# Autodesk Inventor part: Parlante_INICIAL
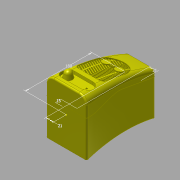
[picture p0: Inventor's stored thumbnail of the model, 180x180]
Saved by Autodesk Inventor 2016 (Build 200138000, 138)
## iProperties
Created: 2013-03
Part Number: Parlante_INICIAL
Material: Polycarbonate, Clear
Document SubType Name: Modeling
Designer: julian.chica
Density: 1 g/cm^3
Appearance: Smooth - Yellow
Author: julian.chica
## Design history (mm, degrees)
sketch "Sketch2"
  geometry: L1 (55, 75)-(-55, 75); L2 (-55, 75)-(-55, -75); L3 (-55, -75)-(55, -75); L4 (55, -75)-(55, 75); L5 (55, 75)-(-55, -75); L6 (-55, 75)-(55, -75); 1 further point
  constraints: 12 end point, 2 midpoint, 2 parallel, 1 horizontal, 1 perpendicular
  dimensions: "d0" = 150 distance of L3.end L1.start; "d2" = 110 distance of L1.start L1.end
sketch "Sketch3"
  geometry: A1 r 500 centre (0, -425) between (200, 33.258) and (0, 75); 3 further points
  constraints: 2 point on circle, 1 centre point, 1 vertical alignment
  dimensions: "d3" = 500 radius of A1; "d5" = 200 horizontal distance of point (0, 0) A1.start
sketch "Sketch4"
  geometry: L1 (0, 0)-(200, -17.498); L2 (0, 0)-(0, -219.032); 2 further points
  constraints: 4 end point, 1 coincident, 1 vertical, 1 vertical alignment
  dimensions: "d6" = 85 deg angle of L2 L1
workplane "Work Plane1"
sketch "Sketch5"
  geometry: L1 (-40, 50.755)-(40, 50.755); L2 (40, 50.755)-(40, -64.245); L3 (40, -64.245)-(-40, -64.245); L4 (-40, -64.245)-(-40, 50.755); 3 further points
  constraints: 8 end point, 2 parallel, 1 horizontal, 1 midpoint, 1 perpendicular
  dimensions: "d7" = 115 distance between parallel lines of L3 L1; "d10" = 80 distance of L1.start L1.end; "d11" = 40 distance from line of point (0, 0) L4
loft "Loft1" sketch "Sketch5" dims "d12" = 0, "d13" = 90 deg, "d14" = 0, "d15" = 90 deg, "d16" = 0, "d17" = 90 deg
sketch "Sketch6"
  geometry: L1 (210, 13.258)-(104.31, 38.532); L2 (74.895, 38.152)-(33.172, 27.026); L3 (17.712, 25)-(-10, 25); L4 (200, 33.258)-(200, -81.742) reference; L5 (0, 75)-(0, -75) reference; A1 r 60 centre (90.355, -19.822) between (104.31, 38.532) and (74.895, 38.152); A2 r 60 centre (17.712, 85) between (17.712, 25) and (33.172, 27.026); 1 further point
  constraints: 6 end point, 4 point on circle, 4 tangent, 2 centre point, 1 equal radius, 1 horizontal
  dimensions: "d20" = 60 radius of A1; "d21" = 10 distance from line of L1.start L4; "d22" = 10 distance from line of L3.end L5; "d23" = 20 vertical distance of L4.start L1.start; "d24" = 50 vertical distance of L5.start L3.end
extrude_surface "ExtrusionSrf1" dims "d29" = 131.5, "d30" = 0
fillet "Fillet1" dims "d25" = 21.25, "d26" = 10, "d27" = 21.25, "d28" = 10
fillet "Fillet2" dims "d31" = 4
fillet "Fillet3" dims "d32" = 2
shell "Shell2" dims "d176" = 2.5
split "Split2"
  body "Solid1"
feature "Lip3" dims "d177" = 1.9, "d178" = 1.22, "d179" = 0, "d180" = 0.12217, "d181" = 0.12217, "d182" = 1.3
feature "Lip4" dims "d183" = 2, "d184" = 1.2, "d185" = 0, "d186" = 0.06981, "d187" = 0, "d188" = 0.2
workplane "Work Plane2"
sketch "Sketch7"
  geometry: L1 (-25, 47)-(25, 47); L2 (25, 47)-(25, 13); L3 (25, 13)-(-25, 13); L4 (-25, 13)-(-25, 47); L5 (-25, 47)-(25, 13); L6 (25, 47)-(-25, 13); A1 r 17 centre (-25, 30) between (-25, 47) and (-25, 13); A2 r 17 centre (25, 30) between (25, 13) and (25, 47); 3 further points
  constraints: 12 end point, 5 midpoint, 4 point on circle, 2 centre point, 2 parallel, 1 horizontal, 1 perpendicular, 1 vertical alignment
  dimensions: "d54" = 17 radius of A1; "d56" = 50 distance of L1.start L1.end; "d57" = 13 distance from line of L3 point (0, 0)
feature "Rest4" sketch "Sketch7" dims "d189" = 5, "d190" = 0, "d191" = 0, "d192" = 0, "d193" = 0, "d194" = 10 deg, "d195" = 1
workplane "Work Plane3"
sketch "Sketch8"
  geometry: L1 (25, 14)-(-25, 14) reference; 4 further points
  constraints: 1 horizontal alignment, 1 vertical alignment
  dimensions: "d73" = 180 vertical distance of point (-21, 180) point (0, 0); "d74" = 21 horizontal distance of point (-21, 180) point (0, 0); "d75" = 21 horizontal distance of point (0, 29) point (21, 180); "d196" = 15 distance from line of L1 point (0, 29)
feature "Boss3" dims "d197" = 0, "d198" = 0, "d199" = 8, "d200" = 3, "d201" = 9.5, "d202" = 1.5 deg, "d203" = 1 deg, "d206" = 2, "d207" = 2, "d208" = 5, "d209" = 0, "d210" = 9 deg, "d211" = 1.5 deg, "d212" = 0.25, "d213" = 0, "d214" = 0, "d215" = 360 deg
feature "Boss4" dims "d216" = 0, "d217" = 0, "d218" = 9, "d219" = 2, "d220" = 0.5, "d221" = 8.1, "d222" = 1.25, "d223" = 3.5, "d224" = 2.5 deg, "d225" = 2.5 deg, "d226" = 2.5 deg, "d227" = 2.5 deg, "d228" = 90 deg, "d231" = 1.5, "d232" = 2, "d233" = 5, "d234" = 0, "d235" = 9 deg, "d236" = 1 deg, "d237" = 0.25, "d238" = 0, "d239" = 0, "d240" = 360 deg
workplane "Work Plane4"
sketch "Sketch9" dims "d131" = 10, "d154" = 10
  geometry: L1 (-37.5, 120)-(37.5, 120); L2 (37.5, 120)-(37.5, 70); L3 (27.5, 60)-(-27.5, 60); L4 (-37.5, 70)-(-37.5, 120); L5 (-37.5, 120)-(37.5, 60); L6 (37.5, 120)-(-37.5, 60); L7 (0, 49.71)-(0, 187.485); L8 (-47.214, 175.937)-(0, 152.413); L9 (-47.214, 169.937)-(0, 146.413); L10 (-47.214, 163.937)-(0, 140.413); L11 (-47.214, 157.937)-(0, 134.413); L12 (-47.214, 151.937)-(0, 128.413); L13 (-47.214, 145.937)-(0, 122.413); L14 (-47.214, 139.937)-(0, 116.413); L15 (-47.214, 133.937)-(0, 110.413); L16 (-47.214, 127.937)-(0, 104.413); L17 (-47.214, 121.937)-(0, 98.413); L18 (-47.214, 115.937)-(0, 92.413); L19 (-47.214, 109.937)-(0, 86.413); L20 (-47.214, 103.937)-(0, 80.413); L21 (-47.214, 97.937)-(0, 74.413); L22 (47.214, 175.937)-(0, 152.413); L23 (47.214, 169.937)-(0, 146.413); L24 (47.214, 151.937)-(0, 128.413); L25 (47.214, 145.937)-(0, 122.413); L26 (47.214, 139.937)-(0, 116.413); L27 (47.214, 133.937)-(0, 110.413); L28 (47.214, 163.937)-(0, 140.413); L29 (47.214, 157.937)-(0, 134.413); L30 (47.214, 127.937)-(0, 104.413); L31 (47.214, 121.937)-(0, 98.413); L32 (47.214, 109.937)-(0, 86.413); L33 (47.214, 103.937)-(0, 80.413); L34 (47.214, 115.937)-(0, 92.413); L35 (47.214, 97.937)-(0, 74.413); L36 (-21, 168.94)-(-21, 53.316); L37 (21, 168.94)-(21, 53.316); L38 (-47.214, 91.937)-(0, 68.413); L39 (47.214, 91.937)-(0, 68.413); L40 (-47.214, 85.937)-(0, 62.413); L41 (47.214, 85.937)-(0, 62.413); L42 (-47.214, 79.937)-(0, 56.413); L43 (47.214, 79.937)-(0, 56.413); L44 (-47.214, 73.937)-(0, 50.413); L45 (47.214, 73.937)-(0, 50.413); L46 (-7.717, 126.838)-(0, 122.994); L47 (-7.577, 125.17)-(0, 121.395); L48 (0, 121.395)-(7.577, 125.17); L49 (0, 122.994)-(7.717, 126.838); A1 r 37.5 centre (0, 120) between (37.5, 120) and (-37.5, 120); A2 r 10 centre (-27.5, 70) between (-37.5, 70) and (-27.5, 60); A3 r 10 centre (27.5, 70) between (27.5, 60) and (37.5, 70); A4 r 10 centre (-17.577, 125.17) between (-7.717, 126.838) and (-7.577, 125.17); A5 r 10 centre (17.577, 125.17) between (7.577, 125.17) and (7.717, 126.838); 5 further points
  constraints: 98 end point, 19 symmetric about line, 10 point on circle, 8 point on line, 7 parallel, 5 centre point, 4 midpoint, 4 tangent, 3 vertical, 1 equal radius, 1 horizontal, 1 perpendicular, 1 vertical alignment, 60 other
  dimensions: "d122" = 75 distance of L5.end L6.end; "d123" = 60 distance of L1.end L5.end; "d124" = 60 distance from line of point (0, 0) L3; "d125" = 10 radius of A2; "d128" = 6 distance of L8.start L9.start; "d133" = 21 distance from line of point (0, 0) L36; "d151" = 6 distance of L21.start L38.start; "d156" = 20 diameter of A4
feature "Grill3" sketch "Sketch9" dims "d241" = 4, "d242" = 0, "d243" = 1, "d244" = 3, "d245" = 2.5, "d246" = 4, "d247" = 0, "d248" = 0, "d249" = 2.5, "d250" = 0, "d251" = 0, "d252" = 0, "d253" = 300.09496
workplane "Work Plane6"
sketch "Sketch10"
  geometry: A1 r 16 centre (0, -16) between (0, 0) and (0, -32) reference; 1 further point
workplane "Work Plane5"
sketch "Sketch11"
  geometry: L1 (0, 0)-(-2, 0); L2 (-2, 0)-(-2, -3.353); L3 (-2, -3.353)-(0, -3.353); L4 (0, -3.353)-(0, 0); 1 further point
  constraints: 8 end point, 2 parallel, 1 horizontal, 1 perpendicular
  dimensions: "d171" = 2 distance between parallel lines of L4 L2
revolve "Revolution3" sketch "Sketch11" stored, may be unused: angle "d256" = 90 deg
mirror "Mirror2"
sketch "Sketch13"
  geometry: L1 (-2, -1)-(-2, 0) reference; L2 (2, -1)-(2, 0) reference; L3 (-17, -1)-(17, -1) reference; L4 (0, -1)-(0, 19.543); L5 (-9.075, 12.181)-(-11.451, 0.902); L6 (-11.451, 0.902)-(-1.674, 0.902); L7 (-1.674, 0.902)-(-1.674, -1); L8 (0, -1)-(-1.674, -1); A1 r 9.274 centre (0, 10.269) between (0, 19.543) and (-9.075, 12.181); 1 further point
  constraints: 10 end point, 3 perpendicular, 2 point on circle, 2 point on line, 1 centre point, 1 collinear, 1 midpoint, 1 tangent
revolve "Revolution4" sketch "Sketch13" stored, may be unused: angle "d257" = 90 deg
body "Srf2"
node "Perilla"
node "frontal"
node "trasero"
other parameters: "d46" = 64.5, "d72" = 6.75, "d121" = 76, "d254" = 4, "d255" = 2.5
